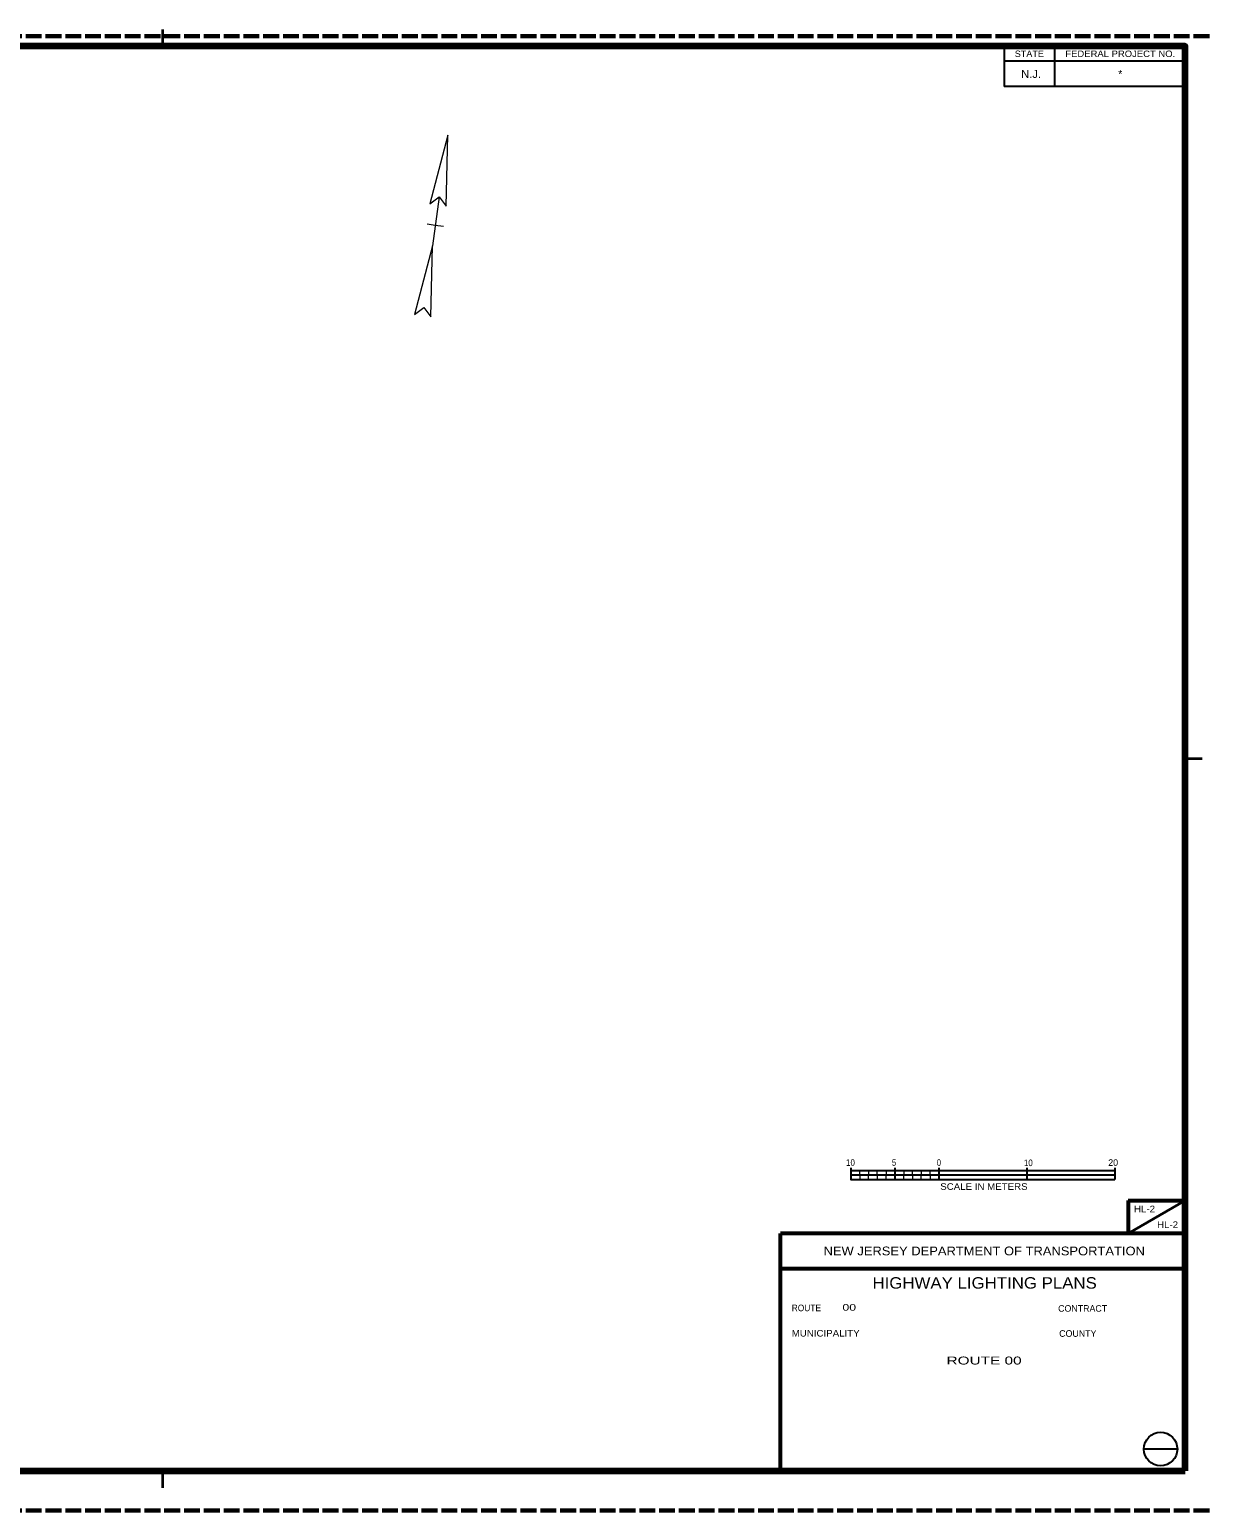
# Model space of a CAD drawing. Extents: x 168423 to 169396, y 223543 to 223937.
# Drawn here: x 169261.9 to 169396.1, y 223542.6 to 223711 of the extents above; entities that cross this region are included whole.
import ezdxf
from ezdxf.enums import TextEntityAlignment as Align

# ---------------------------------------------------------------- set-up
doc = ezdxf.new("R2010")
doc.units = 0
doc.header["$LTSCALE"] = 0.3
doc.linetypes.add('LONG_DASHED', pattern=[7.5, 6, -1.5])
for name, color, linetype, lineweight in [('1', 7, 'Continuous', 13), ('12', 7, 'Continuous', 13), ('25', 7, 'Continuous', 35)]:
    doc.layers.add(name, color=color, linetype=linetype, lineweight=lineweight)

msp = doc.modelspace()

# ---------------------------------------------------------------- linework, layer by layer
at = {"layer": '1', "linetype": 'LONG_DASHED', "lineweight": 60}
for p, q in [((169396.0594, 223710.2685), (169127.8354, 223710.2685)), ((169396.0594, 223542.6285), (169127.8354, 223542.6285))]:
    msp.add_line(p, q, dxfattribs=at)
at = {"layer": '1', "lineweight": 35}
for p, q in [((169277.0594, 223711.0185), (169277.0594, 223709.1285)), ((169393.3094, 223628.1285), (169395.2294, 223628.1285)), ((169277.0594, 223547.1285), (169277.0594, 223545.2085))]:
    msp.add_line(p, q, dxfattribs=at)
at = {"layer": '1', "lineweight": 25}
for p, q in [((169372.7354, 223709.1285), (169372.7354, 223704.5565)), ((169378.4504, 223709.1285), (169378.4504, 223704.5565)), ((169393.3094, 223707.414), (169372.7354, 223707.414)), ((169393.3094, 223704.5565), (169372.7354, 223704.5565)), ((169360.3094, 223581.5667), (169360.3094, 223580.2692)), ((169365.3094, 223581.5667), (169365.3094, 223580.2692)), ((169375.3094, 223581.5667), (169375.3094, 223580.2692)), ((169385.3094, 223581.5667), (169385.3094, 223580.2692)), ((169355.3094, 223581.2692), (169385.3094, 223581.2692)), ((169355.3094, 223580.7692), (169385.3094, 223580.7692)), ((169357.1494, 223581.2692), (169358.1694, 223581.2692)), ((169359.1894, 223581.2692), (169360.2094, 223581.2692)), ((169361.2294, 223581.2692), (169362.2494, 223581.2692)), ((169363.2694, 223581.2692), (169364.2894, 223581.2692))]:
    msp.add_line(p, q, dxfattribs=at)
at = {"layer": '1'}
for p, q in [((169308.5067, 223692.0172), (169307.7335, 223686.4228)), ((169308.0564, 223688.759), (169307.1255, 223688.8877)), ((169308.9873, 223688.6303), (169308.0564, 223688.759))]:
    msp.add_line(p, q, dxfattribs=at)
at = {"layer": '1', "lineweight": 158}
msp.add_lwpolyline([(169393.3094, 223547.1285), (169393.3094, 223709.1285), (169160.8094, 223709.1285), (169160.8094, 223547.1285)], close=True, dxfattribs=at)
at = {"layer": '1'}
for points in [[(169307.4471, 223691.2149), (169308.5067, 223692.0172), (169309.309, 223690.9576), (169309.473, 223699.008)], [(169305.7076, 223678.6298), (169306.7672, 223679.432), (169307.5695, 223678.3724), (169307.7335, 223686.4228)], [(169355.3094, 223580.7692), (169356.3094, 223580.7692), (169356.3094, 223581.2692), (169355.3094, 223581.2692)], [(169356.3094, 223580.2692), (169357.3094, 223580.2692), (169357.3094, 223580.7692), (169356.3094, 223580.7692)], [(169357.3094, 223580.7692), (169358.3094, 223580.7692), (169358.3094, 223581.2692), (169357.3094, 223581.2692)], [(169358.3094, 223580.2692), (169359.3094, 223580.2692), (169359.3094, 223580.7692), (169358.3094, 223580.7692)], [(169359.3094, 223580.7692), (169360.3094, 223580.7692), (169360.3094, 223581.2692), (169359.3094, 223581.2692)], [(169360.3094, 223580.2692), (169361.3094, 223580.2692), (169361.3094, 223580.7692), (169360.3094, 223580.7692)], [(169361.3094, 223580.7692), (169362.3094, 223580.7692), (169362.3094, 223581.2692), (169361.3094, 223581.2692)], [(169362.3094, 223580.2692), (169363.3094, 223580.2692), (169363.3094, 223580.7692), (169362.3094, 223580.7692)], [(169363.3094, 223580.7692), (169364.3094, 223580.7692), (169364.3094, 223581.2692), (169363.3094, 223581.2692)], [(169364.3094, 223580.2692), (169365.3094, 223580.2692), (169365.3094, 223580.7692), (169364.3094, 223580.7692)], [(169365.3094, 223580.7692), (169375.3094, 223580.7692), (169375.3094, 223581.2692), (169365.3094, 223581.2692)], [(169375.3094, 223580.2692), (169385.3094, 223580.2692), (169385.3094, 223580.7692), (169375.3094, 223580.7692)]]:
    msp.add_lwpolyline(points, close=True, dxfattribs=at)
at = {"layer": '1', "lineweight": 25}
msp.add_lwpolyline([(169355.3094, 223581.5667), (169355.3094, 223580.2692), (169385.3094, 223580.2692)], dxfattribs=at)
at = {"layer": '25'}
msp.add_line((169386.8094, 223574.1285), (169393.3094, 223577.8785), dxfattribs=at)
at = {"layer": '25', "lineweight": 53}
for p, q in [((169386.8094, 223577.8785), (169393.3094, 223577.8785)), ((169386.8094, 223577.8785), (169386.8094, 223574.1285)), ((169347.3094, 223547.1285), (169347.3094, 223574.1285)), ((169393.3094, 223574.1285), (169347.3094, 223574.1285)), ((169347.3094, 223570.1285), (169393.3094, 223570.1285))]:
    msp.add_line(p, q, dxfattribs=at)
at = {"layer": '25', "lineweight": 25}
msp.add_line((169388.5994, 223549.6185), (169392.4094, 223549.6185), dxfattribs=at)
msp.add_circle((169390.5125, 223549.6024), 1.9049, dxfattribs=at)

# ---------------------------------------------------------------- texts
at = {"layer": '1'}
for s, height, width, p in [('STATE', 0.7315, 1.05, (169375.5929, 223707.9055)), ('FEDERAL PROJECT NO.', 0.7315, 1.1, (169385.9289, 223707.9055)), ('N.J.', 0.9144, 1.05, (169375.7909, 223705.528)), ('10', 0.7501, 0.9, (169355.2602, 223581.8092)), ('5', 0.7501, 0.75, (169360.212, 223581.8092)), ('0', 0.7501, 0.85, (169365.3145, 223581.8092)), ('10', 0.7501, 0.9, (169375.4803, 223581.7792)), ('SCALE IN METERS', 0.7501, 1.1, (169370.4308, 223579.0792))]:
    msp.add_text(s, height=height, dxfattribs=dict(at, width=width)).set_placement(p, align=Align.CENTER)
for s, height, p in [('*', 0.9144, (169385.9289, 223705.5195)), ('20', 0.7501, (169385.1211, 223581.8092))]:
    msp.add_text(s, height=height, dxfattribs=at).set_placement(p, align=Align.CENTER)
at = {"layer": '12', "width": 1.1}
for s, height, p in [('HL-2', 0.75, (169388.6866, 223576.5325)), ('HL-2', 0.75, (169391.3059, 223574.7431)), ('HIGHWAY LIGHTING PLANS', 1.3, (169370.514, 223567.8452))]:
    msp.add_text(s, height=height, dxfattribs=at).set_placement(p, align=Align.CENTER)
at = {"layer": '25'}
for s, height, width, p in [('NEW JERSEY DEPARTMENT OF TRANSPORTATION', 1, 1.1, (169370.4669, 223571.6285)), ('                   ROUTE 00                  ', 0.9, 1.45, (169370.2071, 223559.2185))]:
    msp.add_text(s, height=height, dxfattribs=dict(at, width=width)).set_placement(p, align=Align.CENTER)
for s, width, p in [('ROUTE', 0.95, (169348.5794, 223565.2785)), ('00                        ', 1.4, (169354.3394, 223565.3385)), ('MUNICIPALITY', 1.1, (169348.5794, 223562.3985))]:
    msp.add_text(s, height=0.75, dxfattribs=dict(at, width=width)).set_placement(p)
for s, p in [('CONTRACT', (169378.8669, 223565.2185)), ('COUNTY', (169378.9869, 223562.3685))]:
    msp.add_text(s, height=0.75, dxfattribs=at).set_placement(p)

doc.saveas('drawing.dxf')
